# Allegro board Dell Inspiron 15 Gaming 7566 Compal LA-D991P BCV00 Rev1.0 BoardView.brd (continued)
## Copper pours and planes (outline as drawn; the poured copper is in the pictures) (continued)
SWF_BSNR on BOTTOM (solid shape): 258.96,13.53 258.96,10.61 258.53,10.18 257.29,10.18 256.85,10.61 256.85,13.5 257.26,13.91 258.58,13.91
SWF_BSNR on IN2 (solid shape): 305.42,6.31 305.42,4.31 304.96,3.85 304.33,3.85 304.17,4 304.17,6.39 304.28,6.49 305.24,6.49
SWF_BSNR on IN2 (solid shape): 260.97,13.35 260.97,12.49 260.59,12.11 260.56,12.11 259.14,10.68 257.13,10.68 256.85,10.96 256.85,11.39 257.39,11.93 258.58,11.93 260.03,13.38 260.94,13.38
U2_BOOT1 on BOTTOM (solid shape): 174.46,59.32 174.46,58.66 174.28,58.49 174.28,58.48 174.22,58.42 174.22,58.01 174.89,57.34 174.89,56.42 174.82,56.36 174.71,56.36 173.54,57.52 173.54,59.32 173.57,59.35 174.43,59.35
U2_BOOT2 on BOTTOM (solid shape): 174.89,53.38 174.89,53.1 174.81,53.02 174.81,51.73 174.89,51.65 174.89,51.09 174.84,51.04 173.92,51.04 173.9,51.07 173.9,51.68 174.56,52.34 174.56,53.3 174.71,53.46 174.81,53.46
U2_LGATE1 on BOTTOM (solid shape): 160.84,51.63 160.84,50.94 160.72,50.82 159.9,50.82 159.78,50.94 159.78,51.68 160.16,52.06 160.41,52.06
U2_LGATE1 on BOTTOM (solid shape): 163.2,56.38 163.2,55.36 162.95,55.11 162.57,55.11 162.06,55.62 162.06,56.4 162.16,56.51 163.08,56.51
U2_LGATE1 on IN1 (solid shape): 160.79,51.55 160.79,50.89 160.72,50.82 159.9,50.82 159.78,50.94 159.78,51.81 159.9,51.93 160.41,51.93
U2_LGATE1 on IN1 (solid shape): 163.65,56.51 163.65,56 163.57,55.92 161.94,55.92 161.8,56.07 161.8,56.5 161.94,56.64 163.52,56.64
U2_LGATE2 on BOTTOM (solid shape): 145.5,51.03 145.5,50.74 145.04,50.28 145.04,49.61 144.87,49.43 144.44,49.43 144.28,49.59 144.28,51.04 144.41,51.17 145.36,51.17
U2_LGATE2 on BOTTOM (solid shape): 145.25,56.72 145.25,56.39 144.95,56.09 144.95,55.7 144.78,55.53 144.37,55.53 144.08,55.82 144.08,56.73 144.23,56.89 145.08,56.89
U2_LGATE2 on BOTTOM (solid shape): 174.35,54.27 174.35,54.07 174.32,54.04 173.59,54.04 173.01,53.46 173.01,52.89 172.9,52.78 172.64,52.78 172.53,52.89 172.53,53.91 172.73,54.12 172.97,54.12 173.11,54.09 173.25,54.12 173.31,54.12 173.48,54.28 174.04,54.28 174.09,54.28 174.15,54.3 174.32,54.3
U2_LGATE2 on IN2 (solid shape): 146.22,51.23 146.22,50.73 146.1,50.62 145.45,50.62 144.41,50.62 144.38,50.65 144.38,51.24 144.44,51.31 146.14,51.31
U2_LGATE2 on IN3 (solid shape): 145.63,51.09 145.63,50.74 145.48,50.59 144.46,50.59 144.31,50.74 144.31,51.74 144.4,51.83 144.89,51.83
U2_LGATE2 on IN3 (solid shape): 145.24,56.72 145.24,56.21 144.95,55.92 144.95,55.58 144.81,55.44 144.47,55.44 144.31,55.6 144.31,56 144.05,56.25 144.05,56.71 144.23,56.89 145.08,56.89
U2_LGATE3 on TOP (solid shape): 206.21,57.39 206.21,56.73 205.95,56.48 204.4,56.48 204.35,56.53 204.35,56.68 204.4,56.73 204.67,56.73 204.72,56.72 204.77,56.72 205.12,56.72 205.13,56.73 205.32,56.73 205.65,57.06 205.65,57.09 205.66,57.1 205.71,57.22 205.73,57.36 205.73,57.47 205.8,57.55 206.05,57.55
U2_LGATE3 on BOTTOM (solid shape): 200.54,69.59 200.54,68.57 200.42,68.44 199.27,68.44 199.15,68.57 199.15,69.59 199.27,69.71 200.42,69.71
U2_LGATE3 on BOTTOM (solid shape): 205.97,69.7 205.97,68.86 205.65,68.54 204.84,68.54 204.71,68.67 204.71,69.69 204.84,69.81 205.85,69.81
U2_LGATE3 on IN1 (solid shape): 205.95,69.69 205.95,68.58 205.88,68.51 204.54,68.51 204.33,68.72 204.33,69.23 204.9,69.8 205.84,69.8
U2_LGATE3 on IN1 (solid shape): 206.31,58.51 206.31,56.68 206.03,56.4 205.65,56.4 205.55,56.51 205.55,57.93 205.7,58.08 205.7,58.51 205.75,58.56 206.26,58.56
U2_LGATE3 on IN1 (solid shape): 201.2,69.1 201.2,68.49 200.43,68.49 200.42,68.51 200.26,68.51 199.97,68.8 199.97,69.61 200.14,69.78 200.53,69.78
U2_PHASE1 on BOTTOM (solid shape): 166.25,60.82 166.25,51.68 166.13,51.55 163.59,51.55 163.46,51.68 163.46,56.51 163.2,56.76 160.16,56.76 159.65,56.25 159.65,51.68 159.52,51.55 156.98,51.55 156.85,51.68 156.85,57.27 157.11,57.52 157.87,57.52 158.25,57.9 158.25,59.81 160.03,61.59 165.49,61.59
U2_PHASE1 on BOTTOM (solid shape): 173.24,59.27 173.24,57.55 174.57,56.21 174.57,56.12 174.48,56.02 174.15,56.02 174.1,56.04 174.04,56.04 173.57,56.04 172.63,56.99 172.25,56.99 172.17,57.06 172.17,57.64 172.21,57.67 172.21,59.26 172.27,59.32 173.19,59.32
U2_PHASE2 on TOP (solid shape): 150,58.66 150,56.12 148.6,54.73 148.6,46.85 148.09,46.35 145.42,46.35 145.17,46.6 145.17,49.77 145.81,50.41 145.81,51.68 145.17,52.31 145.17,55.49 146.09,56.41 146.09,58.75 146.25,58.92 149.74,58.92
U2_PHASE2 on BOTTOM (solid shape): 174.34,53.73 174.34,53.62 174.3,53.58 174.3,52.42 173.64,51.76 173.64,51.09 173.36,50.82 172.35,50.82 172.35,51.73 173.31,52.7 173.31,53.59 173.5,53.78 174.2,53.78 174.2,53.79 174.29,53.79
U2_PHASE2 on BOTTOM (solid shape): 155.33,61.71 155.33,57.65 154.57,56.89 148.98,56.89 148.09,56 148.09,45.94 148.01,45.85 146.89,45.85 146.8,45.86 146.7,45.85 145.36,45.85 145.3,45.91 145.3,46.22 145.3,46.22 145.3,50.28 145.81,50.79 145.81,51.43 145.3,51.93 145.3,56 145.68,56.38 145.68,58.41 149.36,62.09 154.95,62.09
U2_PHASE2 on IN2 (solid shape): 148.09,50.17 148.09,46.22 147.96,46.09 145.42,46.09 145.3,46.22 145.3,49.92 145.74,50.36 147.91,50.36
U2_PHASE2 on IN2 (solid shape): 150,58.16 150,57.78 148.09,55.87 148.09,52.31 147.84,52.06 145.42,52.06 145.3,52.19 145.3,56 147.58,58.28 149.87,58.28
U2_PHASE2 on IN2 (solid shape): 175.22,53.36 175.22,53.03 175.09,52.9 174.36,52.9 173.62,52.16 173.62,51.91 173.59,51.88 173.03,51.88 172.98,51.93 172.98,52.39 174.03,53.43 175.14,53.43
U2_PHASE3 on TOP (solid shape): 202.24,56.73 202.88,56.73 203.01,56.61 203.01,56.56 202.96,56.51 200.77,56.51 200.59,56.33 200.34,56.33 200.19,56.48 200.19,57.32 200.29,57.42 201.56,57.42
U2_PHASE3 on TOP (solid shape): 189.87,71.24 189.87,69.71 190.13,69.46 193.18,69.46 193.3,69.33 193.3,68.57 193.68,68.19 205.37,68.19 205.5,68.06 205.5,65.52 205.24,65.27 194.57,65.27 192.67,63.36 189.37,63.36 188.48,64.25 188.48,71.24 188.6,71.36 189.75,71.36
U2_PHASE3 on BOTTOM (solid shape): 194.45,70.98 194.45,68.7 194.95,68.19 205.37,68.19 205.5,68.06 205.5,65.52 205.37,65.4 194.7,65.4 194.07,64.76 194.07,63.62 193.43,62.98 189.37,62.98 188.99,63.36 188.99,70.73 189.49,71.24 194.19,71.24
U2_PHASE3 on IN2 (solid shape): 194.45,70.98 194.45,68.7 194.95,68.19 205.37,68.19 205.5,68.06 205.5,65.52 205.37,65.4 194.7,65.4 194.07,64.76 194.07,63.62 193.43,62.98 189.37,62.98 188.99,63.36 188.99,70.73 189.49,71.24 194.19,71.24
U2_PHASE3 on IN3 (solid shape): 200.82,58.44 200.82,56.63 200.52,56.33 200.26,56.33 200.14,56.45 200.14,58.41 200.19,58.46 200.8,58.46
U2_PHASE3 on IN3 (solid shape): 194.45,70.98 194.45,68.7 194.95,68.19 205.37,68.19 205.5,68.06 205.5,65.52 205.37,65.4 194.7,65.4 194.07,64.76 194.07,63.62 193.43,62.98 189.37,62.98 188.99,63.36 188.99,70.73 189.49,71.24 194.19,71.24
U2_UGATE1 on BOTTOM (solid shape): 155.43,51.37 155.43,50.74 155.31,50.61 154.24,50.61 154.11,50.74 154.11,51.68 154.47,52.03 154.77,52.03
U2_UGATE1 on BOTTOM (solid shape): 170.32,56.25 170.32,55.62 169.81,55.11 168.16,55.11 168.03,55.24 168.03,55.74 168.79,56.51 170.06,56.51
U2_UGATE1 on BOTTOM (solid shape): 175.38,57.99 175.38,56.73 175.4,56.71 175.4,56.43 175.32,56.36 175.18,56.36 175.05,56.48 175.05,57.48 174.41,58.13 174.41,58.31 174.56,58.46 174.91,58.46
U2_UGATE2 on BOTTOM (solid shape): 151.77,56.12 151.77,55.62 151.65,55.49 150,55.49 149.87,55.62 149.87,56.12 150,56.25 151.65,56.25
U2_UGATE2 on BOTTOM (solid shape): 150.85,50.96 150.85,50.37 150.7,50.22 150.7,49.58 150.56,49.44 150.04,49.44 149.76,49.73 149.76,49.89 149.74,49.9 149.74,50.92 149.87,51.04 150.77,51.04
U2_UGATE2 on IN1 (solid shape): 151.38,51.01 151.38,50.54 151.3,50.46 149.9,50.46 149.72,50.64 149.72,51 149.89,51.18 151.21,51.18
U2_UGATE3 on TOP (solid shape): 201.91,56.23 202.01,56.23 202.01,56.22 202.62,56.22 202.68,56.23 202.98,56.23 203.06,56.15 203.06,56.07 202.96,55.97 202.71,55.97 202.66,55.98 202.62,55.98 202.15,55.98 202.14,55.97 202.09,55.97 201.97,55.85 201.02,55.85 200.9,55.97 200.9,56.23 200.96,56.29 201.66,56.29 201.73,56.29 201.8,56.31 201.83,56.31
U2_UGATE3 on BOTTOM (solid shape): 200.54,63.62 200.54,62.73 200.42,62.6 199.4,62.6 199.15,62.86 199.15,63.62 199.27,63.74 200.42,63.74
U2_UGATE3 on BOTTOM (solid shape): 205.62,63.49 205.62,61.46 205.5,61.33 204.99,61.33 204.86,61.46 204.86,63.49 204.99,63.62 205.5,63.62
U2_UGATE3 on IN3 (solid shape): 205.62,62.98 205.62,61.38 205.17,60.92 204.89,60.92 204.78,61.03 204.78,63.24 204.81,63.26 205.34,63.26
U2_UGATE3 on IN3 (solid shape): 202.27,57.57 202.27,56.17 201.97,55.87 201.05,55.87 200.95,55.97 200.95,56.23 201.66,56.94 201.66,57.6 202.24,57.6
UG_3V on BOTTOM (solid shape): 60.59,11.04 60.59,10.18 60.31,9.9 58.91,9.9 58.71,10.1 58.71,10.35 59.16,10.8 59.16,10.97 59.33,11.14 60.49,11.14
UG_3V on BOTTOM (solid shape): 51.65,20.54 51.65,20.28 51.6,20.18 51.58,20.07 51.58,19.35 51.04,18.81 50.84,18.81 50.71,18.94 50.71,19.88 51.01,20.18 51.06,20.18 51.47,20.59 51.6,20.59
UG_5V on TOP (solid shape): 51.42,28.87 51.42,23.08 51.19,22.85 50.81,22.85 50.63,23.03 50.63,23.51 50.33,23.82 50.33,28.95 50.35,28.97 51.32,28.97
UG_5V on BOTTOM (solid shape): 51.58,23.46 51.58,22.9 51.66,22.81 51.66,22.61 51.57,22.52 51.5,22.52 51.37,22.65 51.19,22.65 50.84,23 50.84,23.84 50.96,23.97 51.07,23.97
UG_5V on BOTTOM (solid shape): 51.7,28.82 51.7,27.8 51.57,27.68 50.3,27.68 50.27,27.71 50.26,27.72 50.19,27.82 50.09,27.89 50.08,27.89 49.54,28.44 49.54,28.82 49.67,28.95 51.57,28.95
UG_+1.35VS_VGAP on BOTTOM (solid shape): 145.42,121.28 145.42,120.64 145.3,120.51 144.15,120.51 144.03,120.64 144.03,121.28 144.15,121.4 145.3,121.4
VCORE_B+ on TOP (solid shape): 110.12,130.93 110.12,127.37 109.99,127.24 105.55,127.24 105.42,127.37 105.42,131.18 105.67,131.44 109.61,131.44
VCORE_B+ on TOP (solid shape): 130.18,132.2 130.18,127.5 130.06,127.37 125.1,127.37 124.85,127.63 124.85,129.73 125.02,130.04 124.85,130.34 124.85,131.31 125.1,131.56 128.15,131.56 128.28,131.69 128.28,132.32 128.41,132.45 129.93,132.45
VCORE_B+ on TOP (solid shape): 118.68,132.06 119.14,132.06 119.26,131.94 119.26,131.44 121.29,131.44 121.29,132.06 121.8,132.06 121.8,130.42 121.63,130.24 121.08,130.24 120.68,129.84 120.53,129.5 120.65,129.16 120.66,129.14 120.66,129.12 120.68,129.12 120.7,129.1 120.74,129.02 120.7,128.95 120.68,128.92 120.66,128.92 120.66,128.9 120.65,128.89 120.56,128.74 120.53,128.56 120.53,128.3 120.53,128.3 120.53,127.88 120.02,127.37 115.2,127.37 115.07,127.5 115.07,131.94 115.2,132.07 118.68,132.07
VCORE_B+ on BOTTOM (solid shape): 129.42,130.8 129.42,128.9 130.06,128.26 130.06,127.5 129.93,127.37 128.41,127.37 128.28,127.24 124.98,127.24 124.85,127.37 124.85,128.39 124.98,128.51 126.37,128.51 126.5,128.64 126.5,128.95 126.55,129.06 126.57,129.18 126.57,129.6 127.26,130.29 127.26,131.31 127.52,131.56 128.66,131.56
VCORE_B+ on BOTTOM (solid shape): 110.05,130.74 110.05,127.3 109.86,127.12 109.26,127.12 109.25,127.12 109.1,127.16 108.95,127.12 108.94,127.12 108.63,127.12 108.62,127.12 108.47,127.16 108.32,127.12 108.31,127.12 104.91,127.12 104.78,127.24 104.78,128.26 104.91,128.39 106.31,128.39 106.44,128.51 106.44,128.83 106.49,128.93 106.51,129.05 106.51,129.47 107.2,130.17 107.2,131.18 107.45,131.44 109.36,131.44
VCORE_B+ on BOTTOM (solid shape): 120.66,131.82 120.66,130.42 120.53,130.29 120.53,129.98 120.47,129.73 120.53,129.49 120.53,127.8 119.99,127.26 119.78,127.26 119.75,127.27 119.62,127.28 119.49,127.25 119.48,127.24 119.17,127.24 119.16,127.25 119.01,127.28 118.86,127.25 118.85,127.24 118.54,127.24 118.46,127.27 118.4,127.28 118.25,127.29 118.11,127.24 114.82,127.24 114.69,127.37 114.69,128.39 114.82,128.51 116.21,128.51 116.34,128.64 116.34,128.95 116.39,129.06 116.41,129.18 116.41,129.6 116.72,129.91 116.72,131.05 116.98,131.31 117.48,131.31 118.25,132.07 120.41,132.07
VCORE_B+ on IN1 (solid shape): outline of 778 points within 104.4,127.27 130.18,133.72
VCORE_B+ on IN3 (solid shape): outline of 236 points within 106.18,127.5 129.3,131.05
N50153 on BOTTOM (solid shape): 72.1,86.96 72.1,84.5 72.45,84.14 72.45,83.78 72.35,83.68 71.46,83.68 71.38,83.76 71.38,84.29 71.79,84.7 71.79,86.93 71.89,87.04 72.02,87.04
N13351923 on BOTTOM (solid shape): 72.45,86.96 72.45,86.02 73.37,85.11 73.8,85.11 74,84.9 74,84.09 73.85,83.94 73.09,83.94 72.22,84.8 72.22,86.93 72.32,87.04 72.37,87.04
N19473637 on BOTTOM (solid shape): 146.38,27.3 146.38,25.52 145.81,25.52 145.3,25.01 145.3,23.36 145.11,23.17 144.79,23.17 144.6,23.36 144.6,24.95 144.22,25.33 144.22,27.42 144.41,27.61 146.06,27.61
N120970730 on TOP (solid shape): 127.87,122.57 127.87,120.44 127.85,120.41 126.25,120.41 126.25,123.05 126.37,123.18 127.26,123.18
N120976432 on TOP (solid shape): 104.66,122.67 104.66,120.26 104.53,120.13 103.64,120.13 103.51,120.26 103.51,122.67 103.64,122.8 104.53,122.8
N120976432 on BOTTOM (solid shape): 102.88,125.85 102.88,124.58 103.01,124.45 106.69,124.45 107.58,123.56 107.58,120.13 107.2,119.75 102.12,119.75 101.74,120.13 101.74,125.72 101.99,125.97 102.75,125.97
N121795600 on TOP (solid shape): 125.26,122.77 125.26,120.49 125.13,120.36 124.24,120.36 123.76,120.84 123.76,122.77 123.89,122.9 125.13,122.9
N121795600 on BOTTOM (solid shape): 122.82,125.97 122.82,124.96 123.2,124.58 126.76,124.58 126.88,124.45 126.88,120.26 126.5,119.88 121.17,119.88 120.91,120.13 120.91,124.32 121.42,124.83 121.42,125.47 122.06,126.1 122.69,126.1
N122017994 on TOP (solid shape): 114.56,122.67 114.56,120.39 114.44,120.26 113.55,120.26 113.42,120.39 113.42,122.67 113.55,122.8 114.44,122.8
N122017994 on BOTTOM (solid shape): 112.66,125.97 112.66,124.96 112.91,124.7 116.6,124.7 117.36,123.94 117.36,120.13 117.1,119.88 115.16,119.88 115.16,119.89 114.6,119.89 114.6,119.88 111.77,119.88 111.26,120.39 111.26,125.54 111.82,126.1 112.53,126.1
N123983992 on TOP (solid shape): 77.48,116.58 77.48,110.99 77.23,110.73 75.96,110.73 75.7,110.99 75.7,115.94 76.46,116.7 77.35,116.7
N123983992 on BOTTOM (solid shape): 80.4,118.74 80.4,117.24 80.39,117.24 80.39,116.68 80.4,116.68 80.4,114.45 80.4,114.45 80.4,113.4 79.74,112.74 77.65,111.64 76.55,109.55 76.4,109.4 76.4,108.29 76.05,107.94 74.05,107.94 73.21,108.78 73.21,109.92 73.3,110.01 74.47,110.01 74.67,110.21 74.67,113.89 74.94,114.16 74.94,114.8 76.97,116.83 76.97,118.74 77.35,119.12 80.02,119.12
N123984271 on TOP (solid shape): 135.26,122.75 135.26,119.37 136.28,118.35 136.28,118.1 136.15,117.97 132.22,117.97 131.84,118.35 131.84,120.77 131.86,120.79 131.86,122.57 132.47,123.18 134.83,123.18
N123984271 on BOTTOM (solid shape): 135.09,123.15 136.26,123.15 136.92,122.49 136.92,117.97 136.53,117.59 134.53,117.59 134.53,119.75 133.72,119.75 133.72,117.62 133.69,117.59 131.71,117.59 131.33,117.97 131.33,122.8 131.58,123.05 132.55,123.05 132.83,123.33 134.91,123.33
N123984271 on IN1 (solid shape): 136.03,123.15 136.03,122.16 136.92,121.28 136.92,117.97 136.64,117.69 131.73,117.69 131.58,117.85 131.58,121.02 133.23,122.67 133.23,123.1 133.59,123.46 135.72,123.46
N123984271 on IN3 (solid shape): 134.97,123.64 135.27,123.47 135.58,123.64 135.65,123.64 136.03,123.26 136.03,122.16 136.92,121.28 136.92,117.97 136.53,117.59 131.71,117.59 131.58,117.72 131.58,121.02 133.23,122.67 133.23,123.51 133.36,123.64
N123984459 on TOP (solid shape): 96.94,122.88 96.94,120.23 96.83,120.13 95.74,120.13 95.69,120.18 95.69,123.15 95.72,123.18 96.63,123.18
N123984461 on TOP (solid shape): 94.37,122.55 94.37,120.26 94.24,120.13 93.35,120.13 93.23,120.26 93.23,122.55 93.35,122.67 94.24,122.67
N123984461 on BOTTOM (solid shape): 92.47,125.85 92.47,124.7 92.72,124.45 96.4,124.45 96.53,124.32 96.53,120.39 95.89,119.75 92.11,119.75 92.11,119.76 91.55,119.76 91.55,119.75 88.91,119.75 88.78,119.88 88.78,121.4 88.79,121.41 88.79,121.53 88.78,121.56 88.78,123.18 90.38,124.78 90.43,124.78 91.63,125.97 92.34,125.97
N128803011 on BOTTOM (solid shape): 100.86,11.22 100.86,10.83 100.78,10.76 99.14,10.76 98.66,10.28 96.55,10.28 95.62,9.34 95.62,9.01 94.12,9.01 93.86,9.26 93.86,10.91 94.12,11.17 98.22,11.17 98.32,11.27 100.81,11.27
N128828208 on TOP (solid shape): 117.23,123.05 117.23,120.39 117.1,120.26 116.09,120.26 115.96,120.39 115.96,123.05 116.09,123.18 117.1,123.18
N128828374 on TOP (solid shape): 107.32,123.05 107.32,120.26 107.2,120.13 106.31,120.13 106.18,120.26 106.18,123.05 106.31,123.18 107.2,123.18
N128835022 on TOP (solid shape): 80.15,116.83 80.15,114.93 80.02,114.8 79,114.8 78.11,115.69 78.11,117.85 78.24,117.97 79,117.97
N128835130 on TOP (solid shape): 136.53,122.24 136.53,119.5 136.47,119.43 135.58,119.43 135.46,119.56 135.46,122.23 135.58,122.35 136.42,122.35
N128884081 on TOP (solid shape): 25.05,36.01 25.05,34.69 24.69,34.32 23.57,34.32 23.02,33.77 21.93,33.77 21.73,33.98 20.96,33.98 20.95,33.97 20.17,33.97 19.87,33.67 18.53,33.67 18.32,33.87 18.32,34.74 18.37,34.79 18.86,34.79 18.98,34.66 22.21,34.66 22.74,35.19 24.11,35.19 24.29,35.37 24.29,35.96 24.39,36.06 25,36.06
N128884081 on BOTTOM (solid shape): 23.12,34.79 23.12,33.77 23,33.65 21.85,33.65 21.65,33.85 21.65,34.69 22.01,35.04 22.87,35.04
N128884094 on TOP (solid shape): 22.34,37.4 22.34,37.18 21.99,36.83 21.99,36.82 21.85,36.68 21.85,35.8 21.87,35.79 21.87,35.23 21.63,34.99 18.25,34.99 18.2,35.05 18.2,35.24 18.43,35.47 18.43,36.27 18.35,36.35 18.35,36.9 19.01,37.56 22.18,37.56
N128884094 on BOTTOM (solid shape): 22.86,37.54 24.56,37.54 24.62,37.49 24.62,36.67 24.57,36.61 24.35,36.61 24.34,36.62 24.01,36.62 22.82,35.42 21.93,35.42 21.42,34.92 21.42,33.9 21.16,33.63 18.87,33.63 18.86,33.65 18.04,33.65 17.79,33.9 17.79,35.25 18.02,35.47 18.98,35.47 19.19,35.68 19.19,37.28 19.47,37.56 22.84,37.56
N128884118 on BOTTOM (solid shape): 18.48,32.88 18.6,32.86 18.73,32.88 18.74,32.88 23.35,32.88 24.41,31.83 24.41,31.6 25.28,30.72 25.28,30.66 25.54,30.4 25.54,29.84 24.63,29.84 24.58,29.79 24.22,29.79 23.89,29.45 24.22,29.12 24.58,29.12 24.63,29.07 25.59,29.07 25.59,28.39 25.26,28.06 18.04,28.06 17.79,28.31 17.79,32.63 18.04,32.88 18.47,32.88
N128885024 on BOTTOM (solid shape): 28.77,35.67 28.77,35.48 28.73,35.39 28.71,35.29 28.71,34.86 28.67,34.81 28.56,34.81 28.03,34.28 28.03,32.6 27.9,32.48 27.54,32.48 27.04,31.97 27.02,31.97 27.02,31.96 26.93,31.87 26.65,31.87 26.55,31.97 26.55,32.22 26.68,32.34 26.68,32.35 27.09,32.76 27.09,34.25 27.62,34.79 28,34.87 28.08,35.25 28.58,35.75 28.69,35.75
N128889202 on BOTTOM (solid shape): 143.93,116.35 143.93,115.59 143.8,115.46 141.89,115.46 141.87,115.48 141.87,116.4 141.89,116.42 143.85,116.42
N128889244 on TOP (solid shape): 142.25,125.09 142.25,123.56 142.12,123.43 140.34,123.43 140.22,123.56 140.22,125.09 140.34,125.21 142.12,125.21
N128983344 on TOP (solid shape): 206.41,58.79 206.41,57.93 206.36,57.88 205.52,57.88 205.42,57.78 205.42,57.29 205.06,56.94 204.38,56.94 204.3,57.01 204.3,57.14 204.81,57.65 204.81,58.56 205.06,58.82 206.38,58.82
N129089927 on BOTTOM (solid shape): 261.5,17.06 261.5,16.86 261.26,16.61 260.72,16.61 260.3,16.2 260.3,15.38 260.49,15.19 261.5,15.19 262.16,15.85 262.16,16.63 262.21,16.68 262.32,16.68 262.39,16.6 262.39,15.46 262.06,15.13 262.06,14.54 261.82,14.3 260.73,14.3 260.51,14.09 260.51,12.06 260.36,11.9 259.55,11.9 259.24,12.21 259.24,13.6 258.48,14.37 258.48,16.11 258.72,16.35 259.37,16.35 260.18,17.16 261.4,17.16
N129090627 on BOTTOM (solid shape): 267.47,16.91 268.34,16.91 268.61,16.63 268.61,14.29 266.3,11.98 262.93,11.98 262.9,12 262.9,13.99 264.88,13.99 265.01,14.11 265.01,15.03 264.68,15.36 264.68,16.63 264.73,16.68 264.86,16.68 264.91,16.63 264.91,15.64 265.57,14.98 266.81,14.98 267.12,15.28 267.12,16.02 266.63,16.5 265.82,16.5 265.62,16.7 265.62,17.06 265.69,17.14 267.24,17.14
N130402506 on TOP (solid shape): 247.63,34.64 247.63,34.4 247.21,33.98 246.8,33.98 246.8,32.81 245.86,31.87 245.68,31.87 245.17,31.36 244.13,31.36 243.86,31.63 243.86,32.52 244.13,32.78 244.13,34.58 244.38,34.84 247.43,34.84
N130433988 on BOTTOM (solid shape): 174.51,60.7 174.51,60.06 174.38,59.93 172.35,59.93 172.22,60.06 172.22,60.7 172.35,60.82 174.38,60.82
N130434002 on TOP (solid shape): 166.63,54.85 166.63,53.97 166.51,53.84 163.84,53.84 163.71,53.97 163.71,54.85 163.84,54.98 166.51,54.98
N130435744 on BOTTOM (solid shape): 174.89,50.28 174.89,49.65 174.76,49.52 172.73,49.52 172.6,49.65 172.6,50.28 172.73,50.41 174.76,50.41
N130435872 on TOP (solid shape): 144.79,58.79 144.79,57.27 144.66,57.14 142.38,57.14 142.25,57.27 142.25,57.78 143.39,58.92 144.66,58.92
N130438051 on TOP (solid shape): 193.3,71.24 193.3,69.71 193.18,69.59 191.4,69.59 191.27,69.71 191.27,71.24 191.4,71.36 193.18,71.36
N131436195 on TOP (solid shape): 56.91,35.22 56.91,31.79 56.19,31.79 56.12,31.87 56.12,35.12 56.37,35.37 56.75,35.37
N132541936 on BOTTOM (solid shape): 256.08,25.92 256.08,23.52 255.66,23.1 255.53,23.07 255.43,22.99 254.19,22.99 253.98,23.21 253.98,26.18 254.22,26.42 255.58,26.42
N132753431 on TOP (solid shape): 134.95,131.32 135.65,131.32 135.65,131.84 136.15,131.84 136.15,131.32 136.85,131.32 136.85,131.84 138.72,131.84 139.28,131.28 139.28,127.98 139.24,127.97 138.97,127.63 139.24,127.28 139.28,127.27 139.28,126.25 139.3,126.23 139.3,125.95 139.02,125.67 138.57,125.67 138.26,125.97 136.56,125.97 136.26,125.67 134.96,125.67 133.54,127.09 133.54,127.63 133.57,127.7 133.65,127.73 133.77,127.73 133.87,127.78 134.09,128.16 133.77,128.46 133.7,128.5 133.68,128.56 133.68,128.75 133.54,128.89 133.54,131.36 134.02,131.84 134.95,131.84
N132753431 on BOTTOM (solid shape): 138.87,130.44 138.87,126.13 138.67,125.92 136.64,125.92 136.57,125.86 136.49,125.79 136.42,125.71 136.01,125.3 134.41,125.3 134.2,125.52 134.2,126.43 134.38,126.61 134.91,126.61 135.25,126.95 135.25,128.37 135.39,128.51 135.8,128.51 135.87,128.59 135.87,130.5 136.33,130.95 138.36,130.95
N132753926 on BOTTOM (solid shape): 131.73,126.13 132.45,126.13 132.52,126.05 132.52,125.9 132.5,125.87 130.46,125.87 130.34,126 130.34,126.48 130.39,126.53 131.33,126.53
N132753938 on BOTTOM (solid shape): 135.72,130.9 135.72,130.09 135.54,129.91 133.59,129.91 133.41,130.09 133.41,130.93 133.54,131.05 135.57,131.05
N132753962 on BOTTOM (solid shape): 135.75,129.35 135.75,128.74 135.7,128.69 135.32,128.69 135.09,128.46 135.09,126.99 134.88,126.79 134.76,126.79 134.63,126.91 134.63,129.33 134.76,129.45 135.65,129.45
N132753966 on BOTTOM (solid shape): 134.5,129.35 134.5,126.86 134.43,126.79 134.22,126.79 134.12,126.89 134.12,126.96 134.15,126.99 134.15,128.23 133.74,128.64 133.59,128.64 133.41,128.82 133.41,129.35 133.54,129.48 134.38,129.48
N132754050 on BOTTOM (solid shape): 133.21,129.5 133.21,128.79 133.36,128.64 133.36,127.9 133.54,127.73 133.54,126.96 133.39,126.81 133.28,126.81 133.21,126.89 133.21,127.6 133.19,127.61 133.19,127.71 132.42,128.49 132.42,129.45 132.52,129.56 133.16,129.56
N133034293 on BOTTOM (solid shape): 18.98,36.77 18.98,35.85 18.81,35.68 17.79,35.68 17.66,35.8 17.66,36.31 17.79,36.44 17.92,36.44 18.42,36.95 18.81,36.95

Small or netless copper shapes (teardrops, artwork), in the pictures only: 37 on TOP, 30 on BOTTOM, 2 on IN1, 2 on IN2, 2 on IN3

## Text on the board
Ref Des/Silkscreen Bottom: H20 | H23 | H17 | H3 | H1 | H10 | H4 | H2 | H11 | H5 | H6 | H19 | H12 | H13 | DC | ONLY DDR4 | HDD | HF
User.Comments: LA-D991P | 2016-07-14 | 2017-07-14 | BCV00 | Saijuan
Ref Des/Silkscreen Top: H23 | H17 | H1 | H3 | H10 | H4 | H2 | H11 | H5 | H6 | H19 | H12 | H13 | CS | KB | PWR | HF
User.40: IMPEDANCE
User.41: FIGURE | SIZE | 8.0 | 20.0 | 28.0 | 35.0 | 98.0 | 110.0 | 118.0 | 126.0 | 130.0 | 146.0 | 43.0 | 63.0 | 83.0 | 47.0x24.0 | 51.0x24.0 | 71.0x31.0 | 79.0x31.0 | 93.0x31.0 | 94.0x39.0 | 94.0x83.0 | DRILL CHART: TOP to BOTTOM | ALL UNITS ARE IN MILS | TOLERANCE | +3.0/-3.0 | +2.0/-2.0 | PLATED | NON-PLATED | QTY | 7630 | 19 | 18 | 8 | 3 | 5 | 1 | 2 | 4 | 6
User.42: HR_1_2mm-8L_160328 | 6.7 | 7.6 | 5.1 | 5.8 | 4.5 | 4 | 5 | 5.1/4.1 | 4.5/3.7 | 4.5/4.3 | 5/4.9 | 4/4 | 3.6/3.5 | 3.5/3.7 | 3.5/5.5 | 3.5/7.6 | 3.5/5.9 | L2/L4 | L4/L7 | REF | L2 | L7 | 7 | 5.7 | 4.6 | 5.1/4 | 4.6/5.2 | L5/L7
